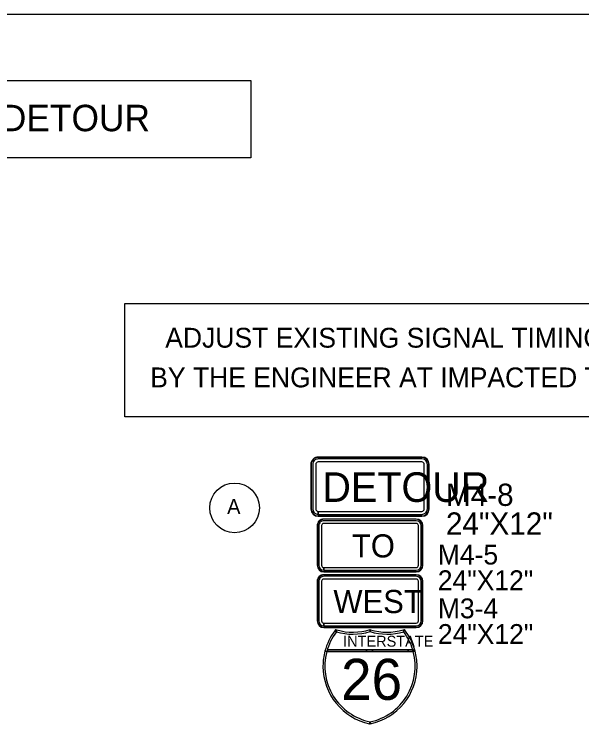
# Model space of a CAD drawing. Extents: x 886234 to 968767, y 455416 to 684046.
# Drawn here: x 931269 to 935566, y 530332 to 535699 of the extents above; entities that cross this region are included whole.
import ezdxf

# ---------------------------------------------------------------- set-up
doc = ezdxf.new("R2010")
doc.units = 0
for name, color, linetype in [('Scratch_Level_3', 7, 'Continuous'), ('TC DEV SIGN BLACK 239', 7, 'Continuous'), ('TC DEV SIGN BLACK ZERO', 7, 'Continuous'), ('TC DEV SIGN ORANGE', 7, 'Continuous'), ('TC DEV SIGN WHITE', 7, 'Continuous'), ('TC LABEL TEXT', 7, 'Continuous')]:
    doc.layers.add(name, color=color, linetype=linetype)

msp = doc.modelspace()

# ---------------------------------------------------------------- linework, layer by layer
at = {"layer": 'Scratch_Level_3'}
msp.add_line((904674.3, 535698.9), (939863.1, 535698.9), dxfattribs=at)
at = {"layer": 'TC DEV SIGN BLACK 239'}
for p, q in [((933575.4, 531409.7), (933575.4, 531109.7)), ((933596.2, 531409.7), (933596.2, 531109.7)), ((934313, 531447.2), (933612.9, 531447.2)), ((934313, 531426.4), (933612.9, 531426.4)), ((934329.7, 531109.7), (934329.7, 531409.7)), ((934350.5, 531109.7), (934350.5, 531409.7)), ((933612.9, 531072.2), (933612.9, 531093)), ((933613.1, 531093), (934313, 531093)), ((933613.1, 531093), (933613.1, 531072.2)), ((933613.1, 531072.2), (934313, 531072.2))]:
    msp.add_line(p, q, dxfattribs=at)
for centre, major_axis, start_param, end_param in [((933612.9, 531409.7), (37.5, 0), 1.570796, 3.141593), ((933612.9, 531409.7), (16.7, 0), 1.570796, 3.141593), ((934313, 531409.7), (37.5, 0), 0, 1.570796), ((934313, 531409.7), (16.7, 0), 0, 1.570796), ((933612.9, 531109.7), (37.5, 0), 3.141593, 4.712389), ((933612.9, 531109.7), (16.7, 0), 3.141593, 4.712389), ((934313, 531109.7), (37.5, 0), 4.712389, 6.283185), ((934313, 531109.7), (16.7, 0), 4.712389, 6.283185)]:
    msp.add_ellipse(centre, major_axis=major_axis, ratio=0.999865, start_param=start_param, end_param=end_param, dxfattribs=at)
at = {"layer": 'TC DEV SIGN BLACK ZERO'}
for p, q in [((934355, 532349.4), (933570.9, 532349.4)), ((933570.9, 532347), (933570.9, 532347.1)), ((934355, 532347), (933570.9, 532347.1)), ((934355, 532335.4), (933570.9, 532335.4)), ((934355, 532347), (934355, 532347)), ((933514.8, 532293.4), (933514.8, 531957.4)), ((933517.2, 532293.4), (933517.2, 531957.4)), ((933517.2, 532293.4), (933517.2, 532293.4)), ((933528.8, 532293.4), (933528.8, 531957.4)), ((933552.2, 532293.4), (933552.2, 531957.4)), ((934355, 532312), (933570.9, 532312)), ((934373.6, 531957.4), (934373.6, 532293.4)), ((934397, 531957.4), (934397, 532293.4)), ((934408.6, 532293.4), (934408.7, 532293.4)), ((934408.7, 531957.4), (934408.7, 532293.4)), ((934411, 531957.4), (934411, 532293.4)), ((933517.2, 531957.4), (933517.2, 531957.4)), ((934408.7, 531957.4), (934408.6, 531957.4)), ((933570.9, 531915.4), (933570.9, 531938.7)), ((933570.9, 531901.4), (933570.9, 531903.7)), ((933570.9, 531903.7), (933570.9, 531903.7)), ((933570.9, 531903.7), (934355, 531903.7)), ((933570.9, 531903.7), (933570.9, 531901.4)), ((933570.9, 531901.4), (934355, 531901.4)), ((933571.1, 531938.7), (934355, 531938.7)), ((933571.1, 531938.7), (933571.1, 531915.4)), ((933571.1, 531915.4), (934355, 531915.4)), ((934355, 531903.7), (934355, 531903.7)), ((934313, 531880.5), (933612.9, 531880.5)), ((933612.9, 531878.5), (933612.9, 531878.5)), ((934313, 531878.4), (933612.9, 531878.5)), ((934313, 531868), (933612.9, 531868)), ((934313, 531847.2), (933612.9, 531847.2)), ((934313, 531878.4), (934313, 531878.5)), ((933562.9, 531830.5), (933562.9, 531530.5)), ((933564.9, 531830.5), (933564.9, 531530.5)), ((933564.9, 531830.5), (933565, 531830.5)), ((933575.4, 531830.5), (933575.4, 531530.5)), ((933596.2, 531830.5), (933596.2, 531530.5)), ((934329.6, 531530.5), (934329.6, 531830.5)), ((934350.5, 531530.5), (934350.5, 531830.5)), ((934360.9, 531830.5), (934360.9, 531830.5)), ((934360.9, 531530.5), (934360.9, 531830.5)), ((934363, 531530.5), (934363, 531830.5)), ((933565, 531530.5), (933564.9, 531530.5)), ((934360.9, 531530.5), (934360.9, 531530.5)), ((933612.9, 531493), (933612.9, 531513.9)), ((933612.9, 531480.5), (933612.9, 531482.6)), ((933612.9, 531482.6), (933612.9, 531482.6)), ((933612.9, 531482.6), (934313, 531482.6)), ((933612.9, 531482.6), (933612.9, 531480.5)), ((933612.9, 531480.5), (934313, 531480.5)), ((933613.1, 531513.9), (934313, 531513.9)), ((933613.1, 531513.9), (933613.1, 531493)), ((933613.1, 531493), (934313, 531493)), ((934313, 531482.6), (934313, 531482.6)), ((933562.9, 531409.7), (933562.9, 531109.7)), ((933565, 531409.7), (933565, 531109.7)), ((933565, 531409.7), (933565, 531409.7)), ((934313, 531459.7), (933612.9, 531459.7)), ((933612.9, 531457.6), (933612.9, 531457.6)), ((934313, 531457.6), (933612.9, 531457.6)), ((934313, 531457.6), (934313, 531457.6)), ((934360.9, 531409.7), (934360.9, 531409.7)), ((934360.9, 531109.7), (934360.9, 531409.7)), ((934363, 531109.7), (934363, 531409.7)), ((933565, 531109.7), (933565, 531109.7)), ((934360.9, 531109.7), (934360.9, 531109.7)), ((933612.9, 531059.7), (933612.9, 531061.8)), ((933612.9, 531061.8), (933612.9, 531061.8)), ((933612.9, 531061.8), (934313, 531061.8)), ((933612.9, 531061.8), (933612.9, 531059.7)), ((933612.9, 531059.7), (934313, 531059.7)), ((933963.3, 531029.8), (933963, 531044.2)), ((934213.7, 531041.4), (934217.7, 531027.1)), ((934313, 531061.8), (934313, 531061.8)), ((933935.8, 530892.3), (933639.9, 530892.3)), ((933639.9, 530877.4), (933935.8, 530877.4)), ((933982.7, 530892.3), (933935.8, 530892.3)), ((933935.8, 530877.4), (933982.7, 530877.4)), ((934251.1, 530892.3), (933982.7, 530892.3)), ((933982.7, 530877.4), (934251.1, 530877.4)), ((934286.1, 530892.3), (934251.1, 530892.3)), ((934251.1, 530877.4), (934286.1, 530877.4)), ((933606.7, 530770.2), (933606.7, 530765.8)), ((934319.2, 530765.7), (934319.2, 530770.4))]:
    msp.add_line(p, q, dxfattribs=at)
for points in [[(933708.2, 531027.1), (933696.4, 531036.1)], [(933712.3, 531041.4), (933708.2, 531027.1)], [(933967.5, 531042.8), (933963.4, 531028.7)], [(934217.7, 531027.1), (934213.7, 531041.4)], [(934223.2, 531044.2), (934223.2, 531044.2), (934223.2, 531044.2)], [(933963, 531028.7), (933963.3, 531029.8)], [(933621.3, 530881.2), (933635.7, 530877.4)], [(933635.7, 530877.4), (933621.3, 530881.2)], [(933639.9, 530892.3), (933639.9, 530877.4)], [(933935.8, 530892.3), (933935.8, 530877.4)], [(933935.8, 530877.4), (933935.8, 530892.3)], [(933982.7, 530892.3), (933982.7, 530877.4)], [(933982.7, 530877.4), (933982.7, 530892.3)], [(934251.1, 530877.4), (934251.1, 530892.3)], [(934251.1, 530892.3), (934251.1, 530877.4)], [(934286.1, 530892.3), (934304.6, 530881.2)], [(934286.1, 530877.4), (934286.1, 530892.3)], [(934304.6, 530881.2), (934290.2, 530877.4)], [(933959.9, 530332.3), (933963, 530346.9)], [(933963, 530346.9), (933963, 530331.7)]]:
    msp.add_lwpolyline(points, dxfattribs=at)
for centre, radius, start, end in [((934052, 530768), 445.3, 142.9968, 165.2769), ((933832.8, 531470.1), 445.3, 254.2907, 286.9893), ((934093.1, 531470.1), 445.3, 253.6206, 285.7093), ((934093.1, 531470.1), 445.3, 285.7093, 286.9901), ((933873.9, 530768), 445.3, 14.7231, 38.3291), ((934052, 530768), 430.5, 142.9968, 165.2769), ((933832.8, 531470.1), 460.2, 254.2907, 286.4259), ((934093.3, 531469.4), 459.4, 253.5731, 285.7093), ((933873.9, 530768), 430.5, 16.7759, 37.0032), ((934052, 530768), 445.3, 165.2769, 179.7177), ((934049.9, 530766.7), 428.8, 165.0438, 258.3001), ((933876, 530766.7), 428.8, 281.7196, 14.964), ((933873.9, 530768), 445.3, 0.2997, 14.7231), ((934052, 530768), 445.3, 180.2823, 258.0591), ((933873.9, 530768), 445.3, 281.537, 359.7003), ((933873.9, 530768), 430.5, 281.9405, 281.9604)]:
    msp.add_arc(centre, radius, start, end, dxfattribs=at)
for centre, major_axis, start_param, end_param in [((933570.9, 532293.4), (56, 0), 1.570796, 3.141593), ((933570.9, 532293.4), (53.7, 0), 1.570796, 3.141593), ((933570.9, 532293.4), (42, 0), 1.570796, 3.141593), ((934355, 532293.4), (56, 0), 0, 1.570796), ((934355, 532293.4), (53.7, 0), 0, 1.570796), ((934355, 532293.4), (42, 0), 0, 1.570796), ((933570.9, 532293.4), (18.7, 0), 1.570796, 3.141593), ((934355, 532293.4), (18.7, 0), 0, 1.570796), ((933570.9, 531957.4), (56, 0), 3.141593, 4.712389), ((933570.9, 531957.4), (53.7, 0), 3.141593, 4.712389), ((933570.9, 531957.4), (42, 0), 3.141593, 4.712389), ((933570.9, 531957.4), (18.7, 0), 3.141593, 4.712389), ((934355, 531957.4), (42, 0), 4.712389, 6.283185), ((934355, 531957.4), (18.7, 0), 4.712389, 6.283185), ((934355, 531957.4), (56, 0), 4.712389, 6.283185), ((934355, 531957.4), (53.7, 0), 4.712389, 6.283185), ((933612.9, 531830.5), (50, 0), 1.570796, 3.141593), ((933612.9, 531830.5), (47.9, 0), 1.570796, 3.141593), ((933612.9, 531830.5), (37.5, 0), 1.570796, 3.141593), ((933612.9, 531830.5), (16.7, 0), 1.570796, 3.141593), ((934313, 531830.5), (50, 0), 0, 1.570796), ((934313, 531830.5), (47.9, 0), 0, 1.570796), ((934313, 531830.5), (37.5, 0), 0, 1.570796), ((934313, 531830.5), (16.7, 0), 0, 1.570796), ((933612.9, 531530.5), (50, 0), 3.141593, 4.712389), ((933612.9, 531530.5), (47.9, 0), 3.141593, 4.712389), ((933612.9, 531530.5), (37.5, 0), 3.141593, 4.712389), ((933612.9, 531530.5), (16.7, 0), 3.141593, 4.712389), ((934313, 531530.5), (37.5, 0), 4.712389, 6.283185), ((934313, 531530.5), (16.7, 0), 4.712389, 6.283185), ((934313, 531530.5), (50, 0), 4.712389, 6.283185), ((934313, 531530.5), (47.9, 0), 4.712389, 6.283185), ((933612.9, 531409.7), (50, 0), 1.570796, 3.141593), ((933612.9, 531409.7), (47.9, 0), 1.570796, 3.141593), ((934313, 531409.7), (50, 0), 0, 1.570796), ((934313, 531409.7), (47.9, 0), 0, 1.570796), ((933612.9, 531109.7), (50, 0), 3.141593, 4.712389), ((933612.9, 531109.7), (47.9, 0), 3.141593, 4.712389), ((934313, 531109.7), (50, 0), 4.712389, 6.283185), ((934313, 531109.7), (47.9, 0), 4.712389, 6.283185)]:
    msp.add_ellipse(centre, major_axis=major_axis, ratio=0.999865, start_param=start_param, end_param=end_param, dxfattribs=at)
at = {"layer": 'TC DEV SIGN ORANGE'}
for p, q in [((934355, 532349.4), (933570.9, 532349.4)), ((933514.8, 532293.4), (933514.8, 531957.4)), ((934411, 531957.4), (934411, 532293.4)), ((933570.9, 531901.4), (934355, 531901.4)), ((934313, 531880.5), (933612.9, 531880.5)), ((933562.9, 531830.5), (933562.9, 531530.5)), ((934363, 531530.5), (934363, 531830.5)), ((933612.9, 531480.5), (934313, 531480.5))]:
    msp.add_line(p, q, dxfattribs=at)
for centre, major_axis, start_param, end_param in [((933570.9, 532293.4), (56, 0), 1.570796, 3.141593), ((934355, 532293.4), (56, 0), 0, 1.570796), ((933570.9, 531957.4), (56, 0), 3.141593, 4.712389), ((934355, 531957.4), (56, 0), 4.712389, 6.283185), ((933612.9, 531830.5), (50, 0), 1.570796, 3.141593), ((934313, 531830.5), (50, 0), 0, 1.570796), ((933612.9, 531530.5), (50, 0), 3.141593, 4.712389), ((934313, 531530.5), (50, 0), 4.712389, 6.283185)]:
    msp.add_ellipse(centre, major_axis=major_axis, ratio=0.999865, start_param=start_param, end_param=end_param, dxfattribs=at)
at = {"layer": 'TC DEV SIGN WHITE'}
for p, q in [((933562.9, 531409.7), (933562.9, 531109.7)), ((934313, 531459.7), (933612.9, 531459.7)), ((934363, 531109.7), (934363, 531409.7)), ((933612.9, 531059.7), (934313, 531059.7)), ((933708.2, 531027.1), (933712.3, 531041.4)), ((933963.4, 531028.7), (933963, 531044.2)), ((933635.7, 530877.4), (934290.2, 530877.4)), ((933635.7, 530877.4), (933639.9, 530877.4)), ((933639.9, 530892.3), (934286.1, 530892.3)), ((934304.6, 530881.2), (934286.1, 530892.3)), ((934289.9, 530878.5), (934286.1, 530877.4)), ((934286.1, 530877.4), (934290.2, 530877.4)), ((933963, 530331.7), (933963, 530346.9))]:
    msp.add_line(p, q, dxfattribs=at)
for points in [[(933696.4, 531036.1), (933708.2, 531027.1)], [(933702.7, 531044.2), (933702.7, 531044.2), (933702.7, 531044.2)], [(933963.3, 531044.1), (933963.3, 531029.8), (933967.5, 531042.8)], [(933639.9, 530877.4), (933639.9, 530892.3)], [(934286.1, 530892.3), (934286.1, 530877.4), (934289.9, 530878.5), (934286.1, 530892.3)], [(934290.2, 530877.4), (934289.9, 530878.5)], [(934290.2, 530877.4), (934304.6, 530881.2)], [(933963, 530346.9), (933959.9, 530332.3), (933962.9, 530331.7)]]:
    msp.add_lwpolyline(points, dxfattribs=at)
for centre, radius, start, end in [((934052, 530768), 445.3, 141.6709, 142.9968), ((933832.8, 531470.1), 445.3, 253.0099, 254.2907), ((934093.1, 531470.1), 445.3, 253.0588, 253.6206), ((934052, 530768), 430.5, 163.2241, 165.2769), ((933873.9, 530768), 430.5, 14.7231, 16.7759), ((934052, 530768), 445.3, 258.458, 258.463), ((933873.9, 530768), 445.3, 281.5369590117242, 281.53700435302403)]:
    msp.add_arc(centre, radius, start, end, dxfattribs=at)
for centre, start_param, end_param in [((933612.9, 531409.7), 1.570796, 3.141593), ((934313, 531409.7), 0, 1.570796), ((933612.9, 531109.7), 3.141593, 4.712389), ((934313, 531109.7), 4.712389, 6.283185)]:
    msp.add_ellipse(centre, major_axis=(50, 0), ratio=0.999865, start_param=start_param, end_param=end_param, dxfattribs=at)
at = {"layer": 'TC LABEL TEXT'}
for points in [[(929678.5, 535197.2), (933060.2, 535197.2), (933060.2, 534613.4), (929678.5, 534613.4)], [(932106.9, 533511.7), (937802.2, 533511.7), (937802.2, 532652.5), (932106.9, 532652.5)]]:
    msp.add_lwpolyline(points, close=True, dxfattribs=at)
msp.add_circle((932937.5, 531964.7), 188.1, dxfattribs=at)

# ---------------------------------------------------------------- texts
at = {"layer": 'TC DEV SIGN BLACK 239'}
msp.add_text('WEST', height=175, rotation=360, dxfattribs=at).set_placement((933685.6, 531169.2))
at = {"layer": 'TC DEV SIGN BLACK ZERO'}
msp.add_text('DETOUR', height=224, dxfattribs=at).set_placement((933601.9, 532010))
for s, height, p in [('M4-8', 168, (934537.7, 531979.9)), ('24"X12"', 168, (934537.7, 531762.6)), ('TO', 175, (933826.1, 531590)), ('M4-5', 150, (934475.9, 531536.5)), ('24"X12"', 150, (934475.9, 531342.5)), ('M3-4', 150, (934476.2, 531129.8)), ('24"X12"', 150, (934476.2, 530935.8)), ('INTERSTATE', 82.13, (933758.9, 530915.3)), ('26', 310.26, (933744, 530513))]:
    msp.add_text(s, height=height, rotation=360, dxfattribs=at).set_placement(p)
at = {"layer": 'TC LABEL TEXT'}
for s, height, p in [('-Y3RPD- DETOUR', 200, (930023.8, 534813.8)), ('ADJUST EXISTING SIGNAL TIMING AS DIRECTED', 150, (932412.7, 533176.7)), ('BY THE ENGINEER AT IMPACTED TRAFFIC SIGNALS', 150, (932299, 532876.7)), ('A', 112.5, (932881.5, 531919.3))]:
    msp.add_text(s, height=height, dxfattribs=at).set_placement(p)

doc.saveas('drawing.dxf')
